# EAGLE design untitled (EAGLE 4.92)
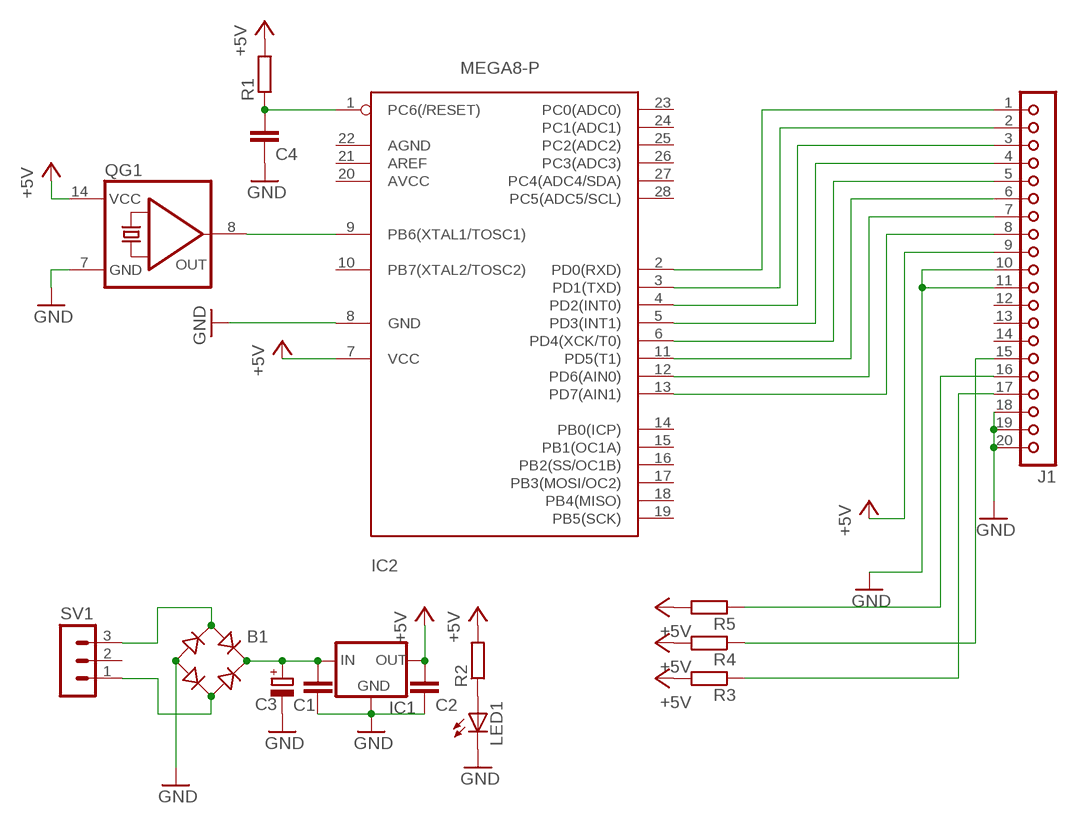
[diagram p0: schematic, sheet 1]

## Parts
B1  RB1A  [RB1A]
C1  C2.5/2  [C2.5-2]
C2  C2.5/2  [C2.5-2]
C3  CPOL-EUE2.5-7  [E2,5-7]
C4  C2.5/2  [C2.5-2]
IC1  78XXS  [78XXS]
IC2  MEGA8-P  [DIL28-3]
J1  JBK20  [JBK20]
LED1  LED3MM  [LED3MM]
QG1  QG5860  [DIL14S]
R1  R-EU_0207/15  [0207/15]
R2  R-EU_0207/12  [0207/12]
R3  R-EU_0207/12  [0207/12]
R4  R-EU_0207/12  [0207/12]
R5  R-EU_0207/12  [0207/12]
SV1  MA03-1  [MA03-1]

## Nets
+5V: C2.1 IC1.OUT IC2.7(VCC) J1.9 QG1.14(VCC) R1.2 R2.2 R3.2 R4.2 R5.2
GND: B1.- C1.2 C2.2 C3.- C4.2 IC1.GND IC2.8(GND) J1.10 J1.11 J1.18 J1.19 J1.20 LED1.K(C) QG1.7(GND)
N$1: IC2.9(PB6(XTAL1/TOSC1)) QG1.8(OUT)
N$2: B1.+ C1.1 C3.+ IC1.IN
N$3: B1.AC1 SV1.3
N$4: C4.1 IC2.1(PC6(/RESET)) R1.1
N$5: B1.AC2 SV1.1
N$6: LED1.A R2.1
N$7: IC2.2(PD0(RXD)) J1.1
N$8: IC2.3(PD1(TXD)) J1.2
N$9: IC2.4(PD2(INT0)) J1.3
N$10: IC2.5(PD3(INT1)) J1.4
N$11: IC2.6(PD4(XCK/T0)) J1.5
N$12: IC2.11(PD5(T1)) J1.6
N$13: IC2.12(PD6(AIN0)) J1.7
N$14: IC2.13(PD7(AIN1)) J1.8
N$15: J1.15 R4.1
N$16: J1.16 R5.1
N$17: J1.17 R3.1
Unconnected: IC2.10(PB7(XTAL2/TOSC2)) IC2.14(PB0(ICP)) IC2.15(PB1(OC1A)) IC2.16(PB2(SS/OC1B)) IC2.17(PB3(MOSI/OC2)) IC2.18(PB4(MISO)) IC2.19(PB5(SCK)) IC2.21(AREF) IC2.23(PC0(ADC0)) IC2.24(PC1(ADC1)) IC2.25(PC2(ADC2)) IC2.26(PC3(ADC3)) IC2.27(PC4(ADC4/SDA)) IC2.28(PC5(ADC5/SCL)) J1.12 J1.13 J1.14 SV1.2

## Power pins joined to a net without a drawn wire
AGND: IC2.22(AGND)
AVCC: IC2.20(AVCC)

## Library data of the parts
B1 = rectifier:RB1A: RECTIFIER 1 A
C1 C2 C4 = capacitor-wima:C: CAPACITOR
C3 = resistor:CPOL-EU: POLARIZED CAPACITOR, European symbol
IC1 = v-reg:78XXS: VOLTAGE REGULATOR
IC2 = atmel:MEGA8-P: MICROCONTROLLER 8 Kbytes FLASH, 1 kbytes SRAM, 512 bytes EEPROM, USART, 4-channel 10 bit ADC, 2-channel 8 bit ADC Pin compatible with Atmega48, ATMega88, ATMega168 Source: avr.lbr
J1 = con-lsta:JBK20: PIN HEADER
LED1 = led:LED: LED
QG1 = crystal:QG5860: CRYSTAL RESONATOR
R1-R5 = resistor:R-EU_: RESISTOR, European symbol
SV1 = con-lstb:MA03-1: PIN HEADER

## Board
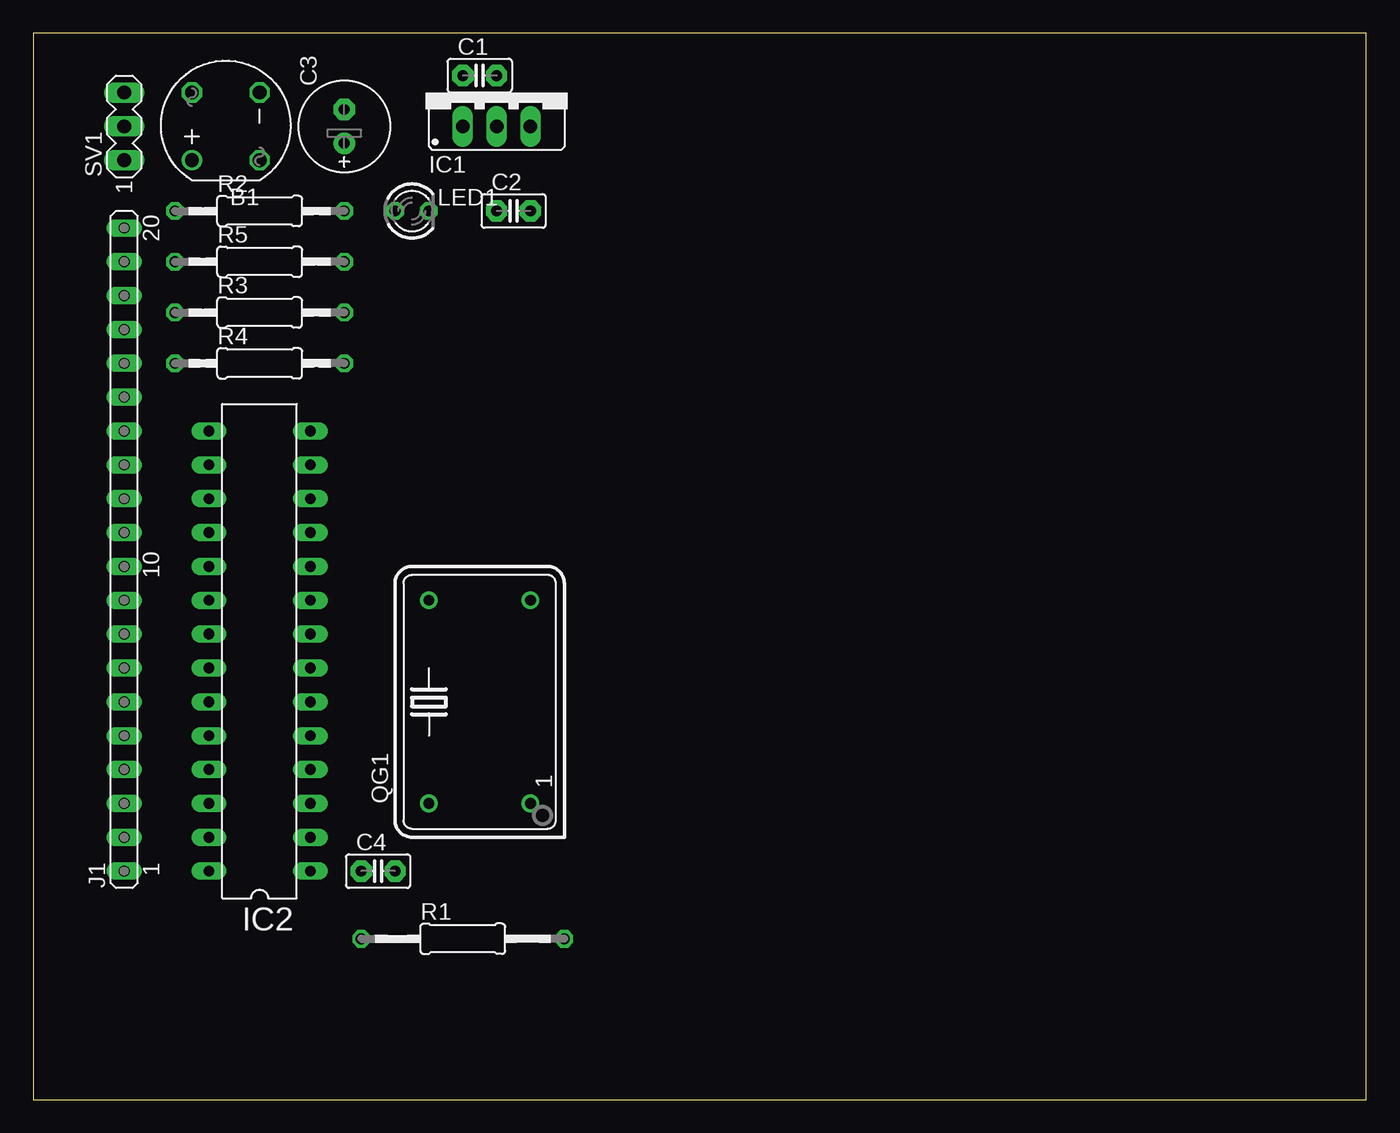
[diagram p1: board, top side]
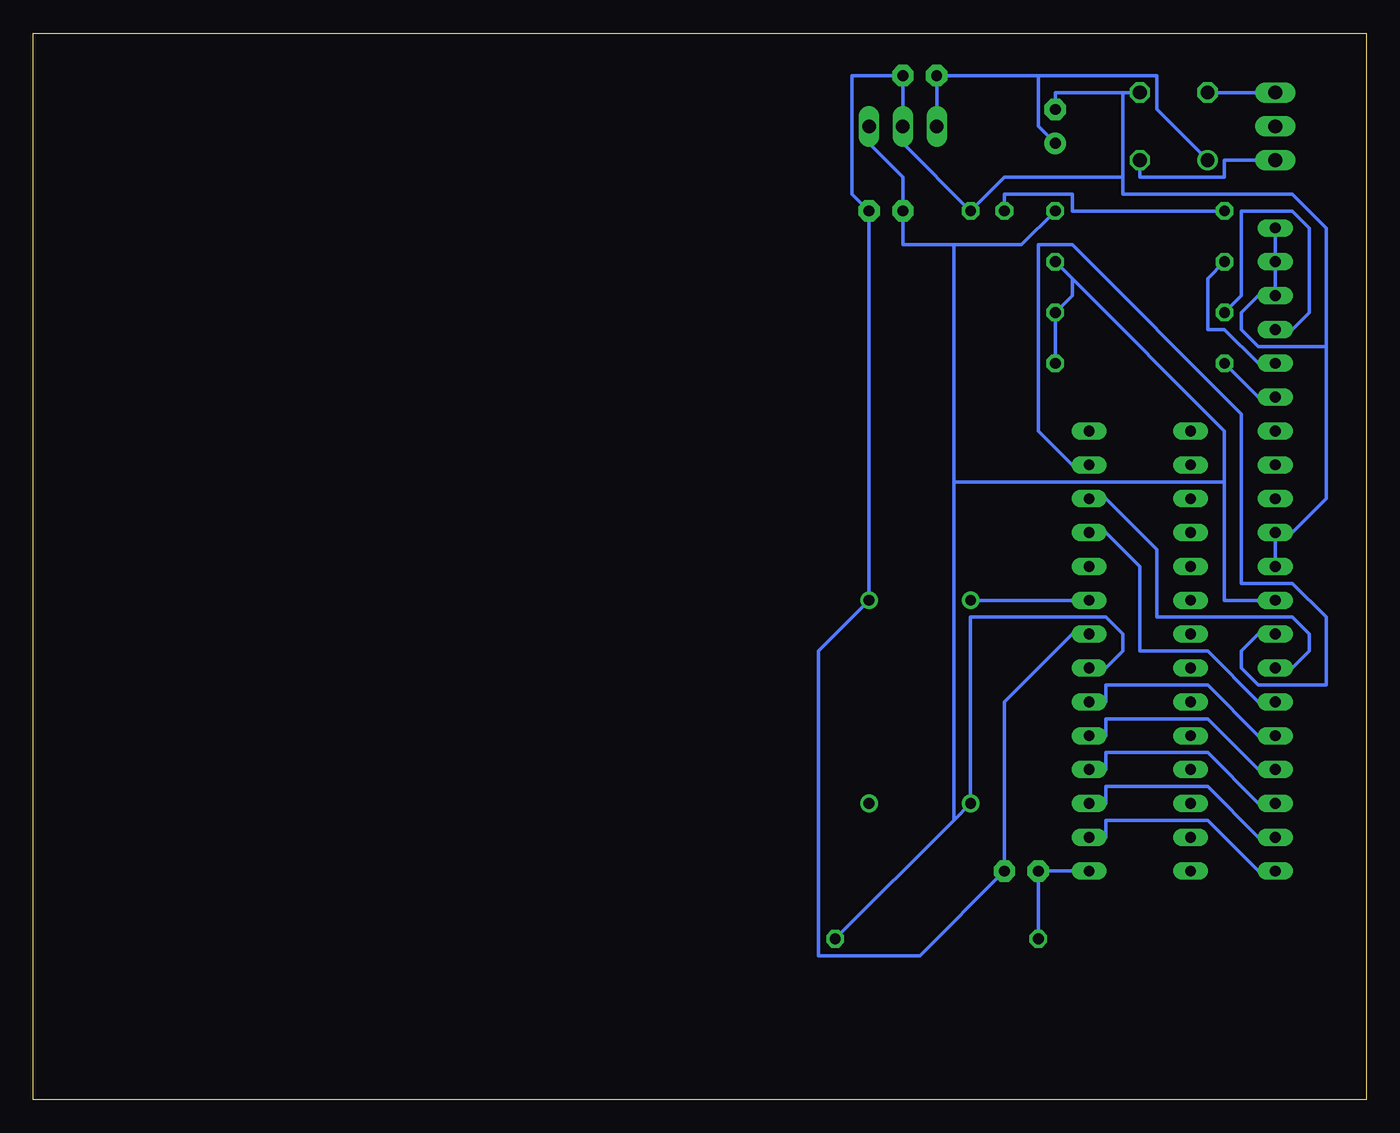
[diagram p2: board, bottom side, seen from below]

Size 100 x 80 mm. Coordinates in mm from the lower left corner, seen from the top.
Outline: 0,0 100,0 100,80 0,80 0,0
Copper layers 16: Bottom 0.035mm
Design rules "default *": minimum track width 10mil, minimum drill 24mil, track to track 8mil, track to pad 8mil, pad to pad 8mil, via to via 8mil, smd to smd 8mil, copper to edge 40mil, drill to drill 8mil, minimum pad ring 10mil, minimum via ring 8mil, stop-mask expansion 4mil, vias tented up to drill 0mil, thermal gap 10mil

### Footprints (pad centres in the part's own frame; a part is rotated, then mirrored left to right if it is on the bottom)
RB1A = drill 1.016 round: + -2.54,2.54 | drill 1.016 octagon: - 2.54,-2.54; AC1 2.54,2.54; AC2 -2.54,-2.54
C2.5-2 = drill 0.813 pad 1.6 octagon: 1 -1.27,0; 2 1.27,0
E2,5-7 = drill 0.813 pad 1.6 round: + -1.27,0 | drill 0.813 pad 1.6 octagon: - 1.27,0
78XXS = drill 1.016 long: GND 0,-2.54; IN -2.54,-2.54; OUT 2.54,-2.54
DIL28-3 = drill 0.813 long: 1 -16.51,-3.81; 2 -13.97,-3.81; 3 -11.43,-3.81; 4 -8.89,-3.81; 5 -6.35,-3.81; 6 -3.81,-3.81; 7 -1.27,-3.81; 8 1.27,-3.81; 9 3.81,-3.81; 10 6.35,-3.81; 11 8.89,-3.81; 12 11.43,-3.81; 13 13.97,-3.81; 14 16.51,-3.81; 15 16.51,3.81; 16 13.97,3.81; 17 11.43,3.81; 18 8.89,3.81; 19 6.35,3.81; 20 3.81,3.81; 21 1.27,3.81; 22 -1.27,3.81; 23 -3.81,3.81; 24 -6.35,3.81; 25 -8.89,3.81; 26 -11.43,3.81; 27 -13.97,3.81; 28 -16.51,3.81
JBK20 = drill 0.813 long: 1 -24.13,0; 2 -21.59,0; 3 -19.05,0; 4 -16.51,0; 5 -13.97,0; 6 -11.43,0; 7 -8.89,0; 8 -6.35,0; 9 -3.81,0; 10 -1.27,0; 11 1.27,0; 12 3.81,0; 13 6.35,0; 14 8.89,0; 15 11.43,0; 16 13.97,0; 17 16.51,0; 18 19.05,0; 19 21.59,0; 20 24.13,0
LED3MM = drill 0.813 octagon: A -1.27,0; K 1.27,0
DIL14S = drill 0.813 round: 1 -7.62,-3.81; 7 7.62,-3.81; 8 7.62,3.81; 14 -7.62,3.81
0207/15 = drill 0.813 octagon: 1 -7.62,0; 2 7.62,0
0207/12 = drill 0.813 octagon: 1 -6.35,0; 2 6.35,0
MA03-1 = drill 1.016 long: 1 -2.54,0; 2 0,0; 3 2.54,0

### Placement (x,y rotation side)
B1  14.44,73.02 90 top
C1  33.49,76.83 0 top
C2  36.03,66.67 0 top
C3  23.33,73.02 90 top
C4  25.87,17.14 0 top
IC1  34.76,75.56 0 top
IC2  16.98,33.65 90 top
J1  6.82,41.27 90 top
LED1  28.41,66.67 0 top
QG1  33.49,29.84 90 top
R1  32.22,12.06 0 top
R2  16.98,66.67 0 top
R3  16.98,59.05 0 top
R4  16.98,55.24 0 top
R5  16.98,62.86 0 top
SV1  6.82,73.02 90 top

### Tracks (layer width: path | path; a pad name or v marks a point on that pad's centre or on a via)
+5V
  Bottom 0.254: R4.2 R3.2 22.06,60.32 22.06,61.59 | 10.63,46.35 10.63,50.16 22.06,61.59 | 10.63,46.35 10.63,37.46 J1.9 | 22.06,61.59 R5.2 | R2.2 25.87,64.13 30.95,64.13 | 30.95,64.13 34.76,64.13 C2.1 34.76,69.21 37.3,71.75 IC1.OUT | IC2.7 19.52,32.38 18.25,33.65 18.25,34.92 19.52,36.19 29.68,36.19 QG1.14 30.95,20.95 | 30.95,20.95 R1.2 | 30.95,46.35 30.95,20.95 | 30.95,46.35 30.95,64.13 | 10.63,46.35 30.95,46.35
GND
  Bottom 0.254: J1.20 J1.19 J1.18 8.09,60.32 9.36,59.05 9.36,57.78 8.09,56.51 3.01,56.51 | J1.10 J1.11 5.55,42.54 3.01,45.08 3.01,56.51 | 18.25,75.56 23.33,75.56 C3.- | 18.25,75.56 B1.- | 3.01,56.51 3.01,65.4 5.55,67.94 18.25,67.94 18.25,69.21 | 18.25,69.21 18.25,75.56 | 18.25,69.21 27.14,69.21 LED1.K 34.76,71.75 IC1.GND C1.2 38.57,76.83 38.57,67.94 C2.2 QG1.7 41.11,33.65 41.11,10.79 33.49,10.79 C4.2 27.14,29.84 22.06,34.92 IC2.8
N$1
  Bottom 0.254: IC2.9 QG1.8
N$2
  Bottom 0.254: B1.+ 15.71,74.29 15.71,76.83 24.6,76.83 | 24.6,76.83 C1.1 IC1.IN | C3.+ 24.6,73.02 24.6,76.83
N$3
  Bottom 0.254: SV1.3 B1.AC1
N$4
  Bottom 0.254: IC2.1 C4.1 R1.1
N$5
  Bottom 0.254: B1.AC2 16.98,69.21 10.63,69.21 10.63,70.48 SV1.1
N$6
  Bottom 0.254: R2.1 22.06,66.67 22.06,67.94 27.14,67.94 LED1.A
N$7
  Bottom 0.254: J1.1 8.09,17.14 11.9,20.95 19.52,20.95 19.52,19.68 IC2.2
N$8
  Bottom 0.254: J1.2 8.09,19.68 11.9,23.49 19.52,23.49 19.52,22.22 IC2.3
N$9
  Bottom 0.254: J1.3 8.09,22.22 11.9,26.03 19.52,26.03 19.52,24.76 IC2.4
N$10
  Bottom 0.254: J1.4 8.09,24.76 11.9,28.57 19.52,28.57 19.52,27.3 IC2.5
N$11
  Bottom 0.254: J1.5 8.09,27.3 11.9,31.11 19.52,31.11 19.52,29.84 IC2.6
N$12
  Bottom 0.254: J1.6 8.09,29.84 11.9,33.65 16.98,33.65 16.98,40 19.52,42.54 IC2.11
N$13
  Bottom 0.254: J1.7 5.55,32.38 4.28,33.65 4.28,34.92 5.55,36.19 15.71,36.19 15.71,41.27 19.52,45.08 IC2.12
N$14
  Bottom 0.254: J1.8 8.09,34.92 9.36,33.65 9.36,32.38 8.09,31.11 3.01,31.11 3.01,36.19 5.55,38.73 9.36,38.73 9.36,51.43 22.06,64.13 24.6,64.13 24.6,50.16 22.06,47.62 IC2.13
N$15
  Bottom 0.254: R4.1 8.09,52.7 J1.15
N$16
  Bottom 0.254: R5.1 11.9,61.59 11.9,57.78 10.63,57.78 8.09,55.24 J1.16
N$17
  Bottom 0.254: R3.1 9.36,60.32 9.36,66.67 5.55,66.67 4.28,65.4 4.28,59.05 5.55,57.78 J1.17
